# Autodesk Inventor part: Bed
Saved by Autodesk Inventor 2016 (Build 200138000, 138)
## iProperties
Created: 2016-01
Part Number: Bed
Material: Generic
Document SubType Name: Modeling
Designer: John
Density: 1 g/cm^3
Appearance: Default
Author: John
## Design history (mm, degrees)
feature "Base1"
body "Solid1"
